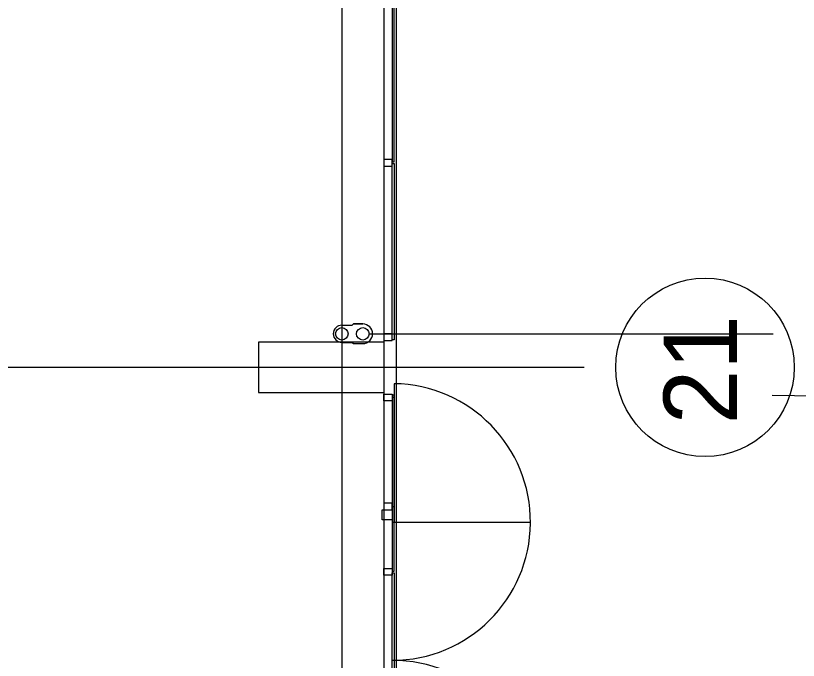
# Model space of a CAD drawing. Extents: x -264205 to -263659, y -1242401 to -1241986.
# Drawn here: x -263799.43 to -263790.1, y -1242220.38 to -1242212.69 of the extents above; entities that cross this region are included whole.
import ezdxf

# ---------------------------------------------------------------- set-up
doc = ezdxf.new("R2010")
doc.units = 0
for name, color, linetype in [('HESCON_OSI_STAVBY_KFA', 7, 'Continuous'), ('PROJEKT_OBRUBNIKY_KOMUNIKACIE', 7, 'Continuous'), ('SITUACIA_DSP_2D', 7, 'Continuous')]:
    doc.layers.add(name, color=color, linetype=linetype)

msp = doc.modelspace()

# ---------------------------------------------------------------- linework, layer by layer
at = {"layer": 'HESCON_OSI_STAVBY_KFA'}
for p, q in [((-263795.5428, -1242083.2372), (-263795.5428, -1242246.7072)), ((-263792.6528, -1242216.8822), (-263857.9132, -1242216.8822)), ((-263792.6528, -1242216.8822), (-263792.6528, -1242216.8822))]:
    msp.add_line(p, q, dxfattribs=at)
msp.add_circle((-263791.2101, -1242216.8825), 1.0643, dxfattribs=at)
at = {"layer": 'PROJEKT_OBRUBNIKY_KOMUNIKACIE'}
msp.add_lwpolyline([(-263794.8928, -1242227.3822), (-263808.9678, -1242241.4572), (-263894.9678, -1242241.4572), (-263909.0427, -1242227.3822), (-263909.0427, -1242196.3327), (-263914.1428, -1242196.3327), (-263914.1428, -1242132.4327), (-263909.0427, -1242132.4327), (-263909.0427, -1242101.3822), (-263894.9678, -1242087.3072), (-263808.9678, -1242087.3072), (-263794.8928, -1242101.3822), (-263794.8928, -1242227.3822)], dxfattribs=at)
at = {"layer": 'SITUACIA_DSP_2D'}
for p, q in [((-263794.8928, -1242101.3822), (-263794.8928, -1242227.3822)), ((-263795.0428, -1242101.7691), (-263795.0428, -1242226.9954)), ((-263794.9427, -1242212.3323), (-263794.9427, -1242214.4323)), ((-263794.9177, -1242214.4323), (-263794.9177, -1242212.3323)), ((-263794.9427, -1242214.4023), (-263795.0427, -1242214.4023)), ((-263795.0427, -1242214.4023), (-263795.0427, -1242214.4823)), ((-263795.0427, -1242214.4823), (-263794.9427, -1242214.4823)), ((-263794.9427, -1242214.4423), (-263794.9427, -1242214.4023)), ((-263794.9427, -1242214.4323), (-263794.9177, -1242214.4323)), ((-263794.9427, -1242214.4823), (-263794.9427, -1242214.4423)), ((-263794.9427, -1242216.5523), (-263794.9427, -1242214.4523)), ((-263794.9427, -1242214.4523), (-263794.9177, -1242214.4523)), ((-263794.9177, -1242214.4523), (-263794.9177, -1242216.5523)), ((-263795.5428, -1242216.3792), (-263795.4178, -1242216.3792)), ((-263795.4178, -1242216.3792), (-263795.4038, -1242216.3652)), ((-263795.2928, -1242216.3652), (-263795.4038, -1242216.3652)), ((-263795.4038, -1242216.3652), (-263795.2928, -1242216.3652)), ((-263795.2178, -1242216.4822), (-263790.3954, -1242216.4822)), ((-263794.9427, -1242216.4823), (-263795.0427, -1242216.4823)), ((-263795.0427, -1242216.4823), (-263795.0427, -1242216.5623)), ((-263794.9427, -1242216.5223), (-263794.9427, -1242216.4823)), ((-263794.9427, -1242216.5623), (-263794.9427, -1242216.5223)), ((-263795.0378, -1242216.5823), (-263796.5378, -1242216.5823)), ((-263796.5378, -1242216.5823), (-263796.5378, -1242217.1823)), ((-263795.5428, -1242216.5852), (-263795.4178, -1242216.5852)), ((-263795.4178, -1242216.5852), (-263795.4038, -1242216.5992)), ((-263795.4038, -1242216.5992), (-263795.2928, -1242216.5992)), ((-263795.0427, -1242216.5623), (-263794.9427, -1242216.5623)), ((-263795.0378, -1242217.1823), (-263795.0378, -1242216.5823)), ((-263794.9177, -1242216.5523), (-263794.9427, -1242216.5523)), ((-263794.9177, -1242217.0775), (-263794.9177, -1242218.7273)), ((-263796.5378, -1242217.1823), (-263795.0378, -1242217.1823)), ((-263795.0427, -1242217.2823), (-263795.0427, -1242217.2023)), ((-263795.0427, -1242217.2023), (-263794.9427, -1242217.2023)), ((-263795.0427, -1242217.2823), (-263795.0427, -1242217.2023)), ((-263795.0427, -1242217.2023), (-263794.9427, -1242217.2023)), ((-263794.9427, -1242217.2823), (-263795.0427, -1242217.2823)), ((-263794.9427, -1242217.2823), (-263795.0427, -1242217.2823)), ((-263794.9427, -1242217.2023), (-263794.9427, -1242217.2423)), ((-263794.9427, -1242217.2023), (-263794.9427, -1242217.2423)), ((-263794.9177, -1242217.2123), (-263794.9427, -1242217.2123)), ((-263794.9427, -1242217.2123), (-263794.9427, -1242219.3123)), ((-263794.9427, -1242217.2423), (-263794.9427, -1242217.2823)), ((-263794.9177, -1242217.2423), (-263794.9427, -1242217.2423)), ((-263794.9427, -1242217.2423), (-263794.9427, -1242218.5423)), ((-263794.9427, -1242217.2423), (-263794.9427, -1242217.2823)), ((-263794.9177, -1242219.3123), (-263794.9177, -1242217.2123)), ((-263794.9177, -1242218.5423), (-263794.9177, -1242217.2423)), ((-263781.8178, -1242217.3754), (-263790.4089, -1242217.2177)), ((-263794.9427, -1242218.5023), (-263795.0427, -1242218.5023)), ((-263795.0427, -1242218.5023), (-263795.0427, -1242218.5823)), ((-263794.9427, -1242218.5423), (-263794.9427, -1242218.5023)), ((-263795.0627, -1242218.7023), (-263795.0627, -1242218.5823)), ((-263795.0627, -1242218.5823), (-263794.9427, -1242218.5823)), ((-263795.0427, -1242218.5823), (-263794.9427, -1242218.5823)), ((-263794.9427, -1242218.5423), (-263794.9177, -1242218.5423)), ((-263794.9427, -1242218.5823), (-263794.9427, -1242218.5423)), ((-263794.9427, -1242218.5823), (-263794.9427, -1242218.7023)), ((-263794.9427, -1242218.7023), (-263795.0627, -1242218.7023)), ((-263794.9427, -1242218.7023), (-263794.9427, -1242218.7273)), ((-263794.9427, -1242218.7273), (-263793.2927, -1242218.7273)), ((-263795.0427, -1242219.3623), (-263795.0427, -1242219.2823)), ((-263795.0427, -1242219.2823), (-263794.9427, -1242219.2823)), ((-263794.9427, -1242219.2823), (-263794.9427, -1242219.3223)), ((-263794.9427, -1242219.3123), (-263794.9177, -1242219.3123)), ((-263794.9427, -1242219.3223), (-263794.9427, -1242219.3623)), ((-263794.9427, -1242221.4323), (-263794.9427, -1242219.3323)), ((-263794.9427, -1242219.3323), (-263794.9177, -1242219.3323)), ((-263794.9177, -1242219.3323), (-263794.9177, -1242221.4323)), ((-263794.9427, -1242219.3623), (-263795.0427, -1242219.3623))]:
    msp.add_line(p, q, dxfattribs=at)
for centre in [(-263795.5428, -1242216.4822), (-263795.2928, -1242216.4822)]:
    msp.add_circle(centre, 0.075, dxfattribs=at)
for centre, radius, start, end in [((-263795.5428, -1242216.4822), 0.103, 90, 270), ((-263795.2928, -1242216.4822), 0.117, 270, 90), ((-263794.9427, -1242218.7273), 1.65, 270, 89.13185), ((-263794.9427, -1242222.0273), 1.65, 270.86815, 90)]:
    msp.add_arc(centre, radius, start, end, dxfattribs=at)

# ---------------------------------------------------------------- texts
at = {"layer": 'HESCON_OSI_STAVBY_KFA'}
msp.add_text('21', height=0.875, rotation=90, dxfattribs=at).set_placement((-263790.8295, -1242217.5623))

doc.saveas('drawing.dxf')
